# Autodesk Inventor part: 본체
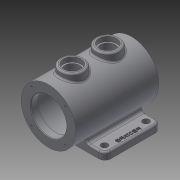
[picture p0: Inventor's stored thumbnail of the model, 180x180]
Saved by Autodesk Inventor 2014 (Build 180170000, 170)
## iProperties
Created: 2014-12
Part Number: 본체
Material: 일반
Document SubType Name: Modeling
Designer: Owner
Density: 1 g/cm^3
Appearance: 기본값
Author: Owner
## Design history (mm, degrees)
sketch "스케치4"
  geometry: L1 (65, -38)-(65, -50); L2 (65, -50)-(-65, -50); L3 (-65, -50)-(-65, -38); L4 (-65, -38)-(-38.884, -38); L5 (38.884, -38)-(65, -38); A1 r 46 centre (0, 0) between (35.072, -29.765) and (-35.072, -29.765); A2 r 5 centre (38.884, -33) between (35.072, -29.765) and (38.884, -38); A3 r 5 centre (-38.884, -33) between (-38.884, -38) and (-35.072, -29.765); 4 further points
  constraints: 10 end point, 8 point on circle, 4 tangent, 3 centre point, 3 parallel, 2 equal length, 2 horizontal, 2 perpendicular, 2 point on line, 1 coincident, 1 equal radius, 1 vertical alignment
  dimensions: "d8" = 92 diameter of A1; "d9" = 12 distance of L1.start L1.end; "d10" = 50 distance from line of L2 point (0, 0); "d11" = 130 distance of L1.end L2.end; "d12" = 5 radius of A2
extrude "돌출3" new body sketch "스케치4" stored distance "d13" = 95; taper "d14" = 0 deg
sketch "스케치5"
  geometry: C1 r 46 at (0, 0); A1 r 46 centre (0, 0) between (35.072, -29.765) and (-35.072, -29.765) reference
  constraints: 1 centre point, 1 coincident, 1 concentric
extrude "돌출4" join sketch "스케치5" distance "d15" = 30; taper "d16" = 0 deg
sketch "스케치6"
  geometry: C1 r 46 at (0, 0); A1 r 46 centre (0, 0) between (-35.072, 29.765) and (35.072, 29.765) reference
  constraints: 1 centre point, 1 coincident, 1 concentric
extrude "돌출5" join sketch "스케치6" distance "d17" = 15; taper "d18" = 0 deg
node "작업 평면2"
sketch "스케치7"
  geometry: L1 (-46, -77.5)-(46, -77.5) reference; C1 r 20 at (0, -37.5); C2 r 20 at (0, 22.5); 1 further point
  constraints: 2 centre point, 2 vertical alignment
  dimensions: "d20" = 40 diameter of C1; "d21" = 40 diameter of C2; "d22" = 40 distance from line of C1.centre L1; "d23" = 60 distance of C2.centre C1.centre
extrude "돌출6" join sketch "스케치7" stored distance "d24" = 15; taper "d25" = 0 deg
sketch "스케치8"
  geometry: C1 r 20 at (0, 0) reference; C2 r 15 at (0, 0); 1 further point
  constraints: 1 centre point, 1 coincident
  dimensions: "d26" = 30 diameter of C2
extrude "돌출7" cut sketch "스케치8" distance "d27" = 8; taper "d28" = 0 deg
sketch "스케치9"
  geometry: C1 r 20 at (0, 0) reference; C2 r 15 at (0, 0); 1 further point
  constraints: 1 centre point, 1 coincident
  dimensions: "d29" = 30 diameter of C2
extrude "돌출8" cut sketch "스케치9" distance "d30" = 8; taper "d31" = 0 deg
sketch "스케치11"
  geometry: C1 r 46 at (0, 0) reference; C2 r 30 at (0, 0)
  constraints: 1 centre point, 1 coincident
  dimensions: "d33" = 60 diameter of C2
extrude "돌출9" cut sketch "스케치11" distance "d34" = 12; taper "d35" = 0 deg
sketch "스케치12"
  geometry: C1 r 46 at (0, 0) reference; C2 r 30 at (0, 0)
  constraints: 1 centre point, 1 coincident
  dimensions: "d36" = 60 diameter of C2
extrude "돌출10" cut sketch "스케치12" distance "d37" = 12; taper "d38" = 0 deg
sketch "스케치13"
  geometry: C1 r 30 at (0, 0) reference; C2 r 37.5 at (0, 0)
  constraints: 1 centre point, 1 coincident
  dimensions: "d39" = 75 diameter of C2
extrude "돌출11" cut sketch "스케치13" distance "d40" = 116; taper "d41" = 0 deg
sketch "스케치14"
  geometry: C1 r 15 at (0, 0) reference; C2 r 12.5 at (0, 0); 1 further point
  constraints: 1 centre point, 1 coincident
  dimensions: "d42" = 25 diameter of C2
extrude "돌출12" cut sketch "스케치14" stored distance "d43" = 116; taper "d44" = 0 deg
sketch "스케치15"
  geometry: C1 r 15 at (0, 0) reference; C2 r 12.5 at (0, 0); 1 further point
  constraints: 1 centre point, 1 coincident
  dimensions: "d45" = 25 diameter of C2
extrude "돌출13" cut sketch "스케치15" stored distance "d46" = 116; taper "d47" = 0 deg
sketch "스케치16"
  geometry: L1 (26.116, 0)-(26.116, -95) reference; L2 (26.116, -95)-(0, -95) reference; C1 r 5.5 at (13.116, -82.5); 1 further point
  constraints: 1 centre point
  dimensions: "d48" = 11 diameter of C1; "d50" = 13 distance from line of C1.centre L1; "d51" = 12.5 distance from line of L2 C1.centre
extrude "돌출14" cut sketch "스케치16" stored distance "d52" = 116; taper "d53" = 0 deg
fillet "모깎기1" dims "d54" = 10
sketch "스케치17"
  geometry: L1 (26.116, 85)-(26.116, 10) reference; C1 r 5.5 at (13.116, 12.5) reference; 2 further points
  constraints: 1 other
  dimensions: "d55" = 35 vertical distance of point (18.116, 47.5) C1.centre; "d56" = 8 distance from line of point (18.116, 47.5) L1
feature "엠보싱1" sketch "스케치17" dims "d8" = 92, "d9" = 12, "d10" = 50, "d11" = 130, "d12" = 5, "d57" = 1, "d58" = 0
sketch "스케치18"
  geometry: L1 (0, 0)-(28.284, 28.284); L2 (0, 0)-(40, 0); C1 r 46 at (0, 0) reference; 1 further point
  constraints: 4 end point, 1 coincident, 1 equal length, 1 horizontal
  dimensions: "d59" = 40 distance of L1.start L1.end; "d60" = 45 deg angle of L2 L1
hole "구멍1" sketch "스케치18" at (28.284, 28.284) diameter "d61" = 3.242; stored, may be unused: countersink angle "d65" = 90 deg, drill point angle "d67" = 118 deg; dims "d62" = 8, "d63" = 4, "d64" = 2, "d66" = 10
sketch "스케치19"
  geometry: L1 (0, 0)-(28.284, 28.284); L2 (0, 0)-(40, 0); C1 r 46 at (0, 0) reference; 1 further point
  constraints: 4 end point, 1 coincident, 1 equal length, 1 horizontal
  dimensions: "d71" = 40 distance of L1.start L1.end; "d72" = 45 deg angle of L2 L1
hole "구멍2" sketch "스케치19" at (28.284, 28.284) diameter "d73" = 3.242; stored, may be unused: countersink angle "d77" = 90 deg, drill point angle "d79" = 118 deg; dims "d74" = 8, "d75" = 4, "d76" = 2, "d78" = 10
fillet "모깎기2" dims "d83" = 3
fillet "모깎기3" dims "d84" = 3
chamfer "모따기1" distance "d85" = 1; stored, may be unused: second distance "d86" = 2, angle "d87" = 45 deg
node "솔리드2"
mirror "대칭1"
mirror "대칭2"
pattern_circular "원형 패턴1" dims angle "d69" = 360 deg
pattern_circular "원형 패턴2" dims angle "d81" = 360 deg
other parameters: "d19" = 56
